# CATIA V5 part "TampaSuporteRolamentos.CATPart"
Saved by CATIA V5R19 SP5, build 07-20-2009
Part number: TampaSuporteRolamentos
Bounding box of the stored display mesh (mm): x -17.5 to 17.5, y 0 to 2, z -17.5 to 17.5
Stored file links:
  Z:\UA\ATLAS\atlascar\ServoPiloto\dir\suportePotenciometro\V2\TampaSuporteRolamentos.CATPart
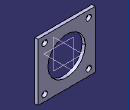
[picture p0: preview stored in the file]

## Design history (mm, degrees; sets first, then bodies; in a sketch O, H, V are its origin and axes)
Body1 (main body)
  Sketch1 on zx-plane, origin (0, 0, 0), H (-1, 0, 0), V (0, 0, 1)
    circle A1 centre (0, 0) radius 11.5
    line L1 (-17.5, 17.5) -> (17.5, 17.5)
    line L2 (17.5, 17.5) -> (17.5, -17.5)
    line L3 (17.5, -17.5) -> (-17.5, -17.5)
    line L4 (-17.5, -17.5) -> (-17.5, 17.5)
    circle A2 centre (13.5, 13.5) radius 1.75
    point P5 (13.5, 13.5)
    circle A3 centre (-13.5, 13.5) radius 1.75
    circle A4 centre (13.5, -13.5) radius 1.75
    circle A5 centre (-13.5, -13.5) radius 1.75
    radius A1 = 11.5
    distance L1 L3 = 35
    distance L2 L4 = 35
    distance L3 H = 17.5 {= Sketch1.distance(L1 L3) /2}
    distance V L2 = 17.5 {= Sketch1.distance(L2 L4) /2}
    radius A2 = 1.75
    distance P5 L2 = 4
    distance L1 P5 = 4
    horizontal: L1 H, L3 H
    vertical: L2 V, L4 V
    symmetry: A2 A3 V, A2 A4 H, A3 A5 H
  Pad1: profile Sketch1, direction (0, 1, 0), length 2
